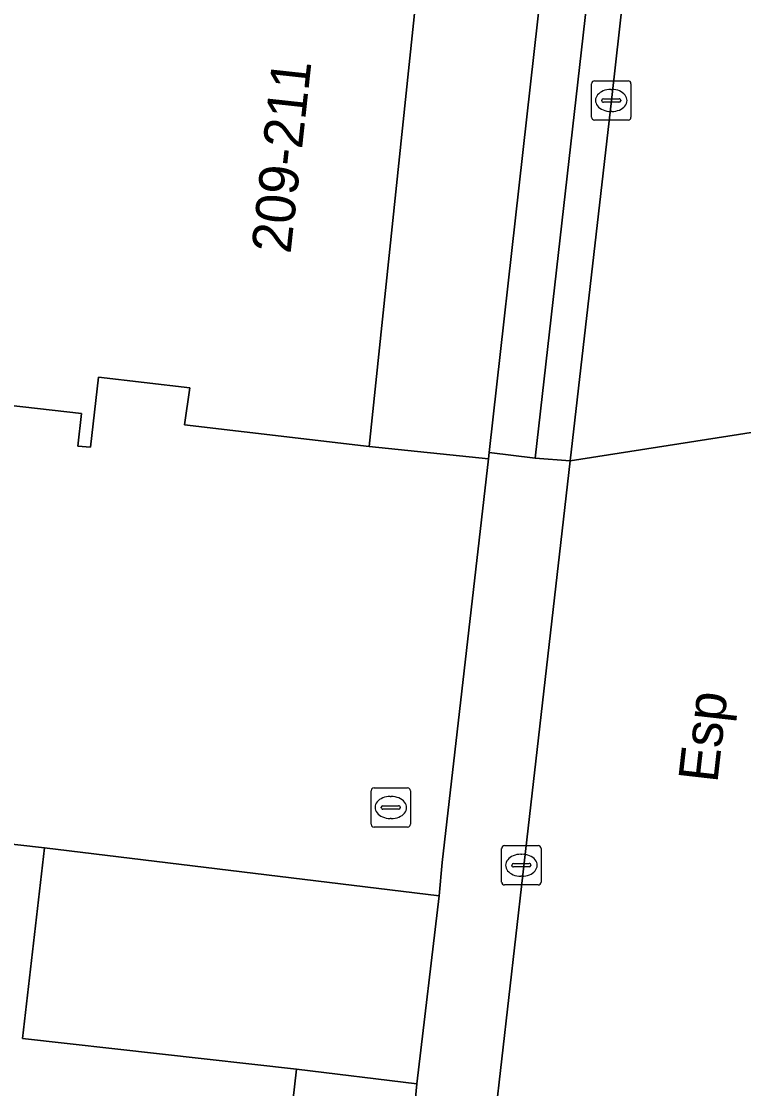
# Model space of a CAD drawing. Extents: x 161385 to 162589, y 388479 to 389756.
# Drawn here: x 162330.1 to 162348.45, y 388767.85 to 388794.97 of the extents above; entities that cross this region are included whole.
import ezdxf

# ---------------------------------------------------------------- set-up
doc = ezdxf.new("R2010")
doc.units = 0
for name, color, linetype in [('IMGEO_Berm_groen', 7, 'Continuous'), ('IMGEO_Erf', 7, 'Continuous'), ('IMGEO_Groenvoorziening', 7, 'Continuous'), ('IMGEO_Kolk', 7, 'Continuous'), ('IMGEO_Openbare_ruimte_label', 7, 'Continuous'), ('IMGEO_Pand', 7, 'Continuous'), ('IMGEO_Pand_nummerreeks', 7, 'Continuous'), ('IMGEO_Rijbaan_lokaal_gesloten', 7, 'Continuous'), ('IMGEO_Rioolput', 7, 'Continuous'), ('IMGEO_Voetpad_open', 7, 'Continuous')]:
    doc.layers.add(name, color=color, linetype=linetype)

msp = doc.modelspace()

# ---------------------------------------------------------------- linework, layer by layer
at = {"layer": 'IMGEO_Berm_groen'}
msp.add_lwpolyline([(162345.085, 388792.96), (162345.796, 388799.312), (162344.909, 388799.405), (162343.152, 388783.876), (162344.038, 388783.802)], close=True, dxfattribs=at)
at = {"layer": 'IMGEO_Erf'}
msp.add_lwpolyline([(162279.747, 388779.705), (162330.688, 388773.968), (162340.71, 388772.751), (162340.788, 388773.594), (162341.961, 388783.856), (162338.936, 388784.171), (162334.24, 388784.715), (162334.379, 388785.658), (162332.058, 388785.932), (162331.85, 388784.151), (162331.535, 388784.179), (162331.623, 388785.008), (162280.589, 388790.807)], dxfattribs=at)
at = {"layer": 'IMGEO_Groenvoorziening'}
msp.add_lwpolyline([(162343.021, 388800.103), (162340.623, 388800.353), (162338.936, 388784.171), (162341.961, 388783.856), (162341.98, 388784.02), (162343.689, 388799.274)], dxfattribs=at)
msp.add_lwpolyline([(162338.562, 388754.139), (162340.077, 388767.261), (162340.139, 388767.971), (162337.086, 388768.346), (162335.369, 388753.18), (162338.455, 388752.823)], close=True, dxfattribs=at)
at = {"layer": 'IMGEO_Kolk'}
for p, q in [((162344.657, 388793.461), (162345.509, 388793.461)), ((162344.582, 388792.535), (162344.582, 388793.387)), ((162345.07, 388793.241), (162345.095, 388793.241)), ((162345.583, 388793.387), (162345.583, 388792.535)), ((162344.841, 388792.955), (162344.841, 388792.967)), ((162345.279, 388792.918), (162344.881, 388792.918)), ((162344.884, 388793.004), (162345.282, 388793.004)), ((162345.325, 388792.967), (162345.325, 388792.955)), ((162345.093, 388792.681), (162345.068, 388792.681)), ((162345.509, 388792.461), (162344.657, 388792.461)), ((162342.298, 388773.102), (162342.298, 388773.954)), ((162342.373, 388774.028), (162343.225, 388774.028)), ((162343.299, 388773.954), (162343.299, 388773.102)), ((162342.786, 388773.808), (162342.811, 388773.808)), ((162342.557, 388773.522), (162342.557, 388773.534)), ((162342.995, 388773.485), (162342.597, 388773.485)), ((162342.6, 388773.571), (162342.998, 388773.571)), ((162343.041, 388773.534), (162343.041, 388773.522)), ((162342.809, 388773.248), (162342.784, 388773.248)), ((162343.225, 388773.028), (162342.373, 388773.028))]:
    msp.add_line(p, q, dxfattribs=at)
for points in [[(162344.657, 388793.461), (162345.509, 388793.461)], [(162344.582, 388792.535), (162344.582, 388793.387)], [(162345.583, 388793.387), (162345.583, 388792.535)], [(162345.509, 388792.461), (162344.657, 388792.461)], [(162342.298, 388773.102), (162342.298, 388773.954)], [(162342.373, 388774.028), (162343.225, 388774.028)], [(162343.299, 388773.954), (162343.299, 388773.102)], [(162343.225, 388773.028), (162342.373, 388773.028)]]:
    msp.add_lwpolyline(points, dxfattribs=at)
for centre, radius, start, end in [((162344.659, 388793.385), 0.0765, 91.552, 178.448), ((162344.659, 388793.385), 0.0765, 91.552, 178.448), ((162345.507, 388793.385), 0.0765, 1.552, 88.448), ((162345.507, 388793.385), 0.0765, 1.552, 88.448), ((162344.881, 388792.964), 0.0403, 85.8775, 175.7526), ((162344.878, 388792.954), 0.0366, 178.938, 274.7102), ((162345.282, 388792.961), 0.043, 264.8664, 352.4533), ((162345.286, 388792.966), 0.0386, 1.7309, 96.639), ((162344.659, 388792.537), 0.0765, 181.552, 268.448), ((162344.659, 388792.537), 0.0765, 181.552, 268.448), ((162345.507, 388792.537), 0.0765, 271.552, 358.448), ((162345.507, 388792.537), 0.0765, 271.552, 358.448), ((162342.375, 388773.952), 0.0765, 91.552, 178.448), ((162342.375, 388773.952), 0.0765, 91.552, 178.448), ((162343.223, 388773.952), 0.0765, 1.552, 88.448), ((162343.223, 388773.952), 0.0765, 1.552, 88.448), ((162342.597, 388773.531), 0.0403, 85.8775, 175.7526), ((162342.594, 388773.521), 0.0366, 178.938, 274.7102), ((162342.998, 388773.528), 0.043, 264.8664, 352.4533), ((162343.002, 388773.533), 0.0386, 1.7309, 96.639), ((162342.375, 388773.104), 0.0765, 181.552, 268.448), ((162342.375, 388773.104), 0.0765, 181.552, 268.448), ((162343.223, 388773.104), 0.0765, 271.552, 358.448), ((162343.223, 388773.104), 0.0765, 271.552, 358.448)]:
    msp.add_arc(centre, radius, start, end, dxfattribs=at)
for centre, major_axis, ratio, start_param, end_param in [((162345.069, 388792.961), (-0.387, 0.002), 0.722429, 4.712389, 7.853982), ((162345.094, 388792.961), (-0.39, 0.002), 0.717154, 1.570796, 4.712389), ((162342.785, 388773.528), (-0.387, 0.002), 0.722429, 4.712389, 7.853982), ((162342.81, 388773.528), (-0.39, 0.002), 0.717154, 1.570796, 4.712389)]:
    msp.add_ellipse(centre, major_axis=major_axis, ratio=ratio, start_param=start_param, end_param=end_param, dxfattribs=at)
at = {"layer": 'IMGEO_Pand'}
for points in [[(162334.332, 388806.326), (162283.02, 388812.167), (162280.589, 388790.807), (162331.623, 388785.008), (162331.535, 388784.179), (162331.85, 388784.151), (162332.058, 388785.932), (162334.379, 388785.658), (162334.24, 388784.715), (162338.936, 388784.171), (162340.623, 388800.353), (162340.638, 388800.493), (162333.756, 388801.193), (162334.321, 388806.194)], [(162335.369, 388753.18), (162337.086, 388768.346), (162330.125, 388769.129), (162330.688, 388773.968), (162279.747, 388779.705), (162277.505, 388759.734)]]:
    msp.add_lwpolyline(points, close=True, dxfattribs=at)
at = {"layer": 'IMGEO_Rijbaan_lokaal_gesloten'}
for points in [[(162364.598, 388917.339), (162355.936, 388879.524), (162354.085, 388871.528), (162350.544, 388841.795), (162349.892, 388835.959), (162348.515, 388823.765), (162348.397, 388822.686), (162347.549, 388814.966), (162346.508, 388805.67), (162345.796, 388799.312), (162345.085, 388792.96), (162344.038, 388783.802), (162351.507, 388784.973), (162351.586, 388785.803), (162354.609, 388813.12), (162354.707, 388814.075), (162359.887, 388860.235), (162360.209, 388863.109), (162360.509, 388865.779), (162360.606, 388866.537), (162361.541, 388871.709), (162361.659, 388872.226), (162367.76, 388898.886)], [(162344.45, 388723.253), (162346.266, 388739.136), (162347.508, 388750), (162351.507, 388784.973), (162344.038, 388783.802), (162342.836, 388773.285), (162342.124, 388767.05), (162340.637, 388753.967), (162340.189, 388750), (162339.087, 388740.255), (162338.482, 388734.9), (162338.192, 388732.338), (162337.703, 388727.976)]]:
    msp.add_lwpolyline(points, dxfattribs=at)
at = {"layer": 'IMGEO_Rioolput'}
for p, q in [((162338.981, 388774.57), (162338.981, 388775.422)), ((162339.056, 388775.496), (162339.908, 388775.496)), ((162339.982, 388775.422), (162339.982, 388774.57)), ((162339.283, 388775.039), (162339.681, 388775.039)), ((162339.469, 388775.276), (162339.494, 388775.276)), ((162339.24, 388774.99), (162339.24, 388775.002)), ((162339.678, 388774.953), (162339.28, 388774.953)), ((162339.724, 388775.002), (162339.724, 388774.99)), ((162339.908, 388774.496), (162339.056, 388774.496)), ((162339.492, 388774.716), (162339.467, 388774.716))]:
    msp.add_line(p, q, dxfattribs=at)
for points in [[(162338.981, 388774.57), (162338.981, 388775.422)], [(162339.056, 388775.496), (162339.908, 388775.496)], [(162339.982, 388775.422), (162339.982, 388774.57)], [(162339.908, 388774.496), (162339.056, 388774.496)]]:
    msp.add_lwpolyline(points, dxfattribs=at)
for centre, radius, start, end in [((162339.058, 388775.42), 0.0765, 91.552, 178.448), ((162339.058, 388775.42), 0.0765, 91.552, 178.448), ((162339.906, 388775.42), 0.0765, 1.552, 88.448), ((162339.906, 388775.42), 0.0765, 1.552, 88.448), ((162339.28, 388774.999), 0.0403, 85.8775, 175.7526), ((162339.685, 388775.001), 0.0386, 1.7309, 96.639), ((162339.277, 388774.989), 0.0366, 178.938, 274.7102), ((162339.681, 388774.996), 0.043, 264.8664, 352.4533), ((162339.058, 388774.572), 0.0765, 181.552, 268.448), ((162339.058, 388774.572), 0.0765, 181.552, 268.448), ((162339.906, 388774.572), 0.0765, 271.552, 358.448), ((162339.906, 388774.572), 0.0765, 271.552, 358.448)]:
    msp.add_arc(centre, radius, start, end, dxfattribs=at)
for centre, major_axis, ratio, start_param, end_param in [((162339.468, 388774.996), (-0.387, 0.002), 0.722429, 4.712389, 7.853982), ((162339.493, 388774.996), (-0.39, 0.002), 0.717154, 1.570796, 4.712389)]:
    msp.add_ellipse(centre, major_axis=major_axis, ratio=ratio, start_param=start_param, end_param=end_param, dxfattribs=at)
at = {"layer": 'IMGEO_Voetpad_open'}
for points in [[(162343.689, 388799.274), (162341.98, 388784.02), (162343.152, 388783.876), (162344.909, 388799.405), (162343.72, 388799.552)], [(162340.788, 388773.594), (162340.71, 388772.751), (162340.139, 388767.971), (162340.077, 388767.261), (162341.289, 388767.134), (162342.124, 388767.05), (162342.836, 388773.285), (162344.038, 388783.802), (162343.152, 388783.876), (162341.98, 388784.02), (162341.961, 388783.856)], [(162340.71, 388772.751), (162330.688, 388773.968), (162330.125, 388769.129), (162337.086, 388768.346), (162340.139, 388767.971)]]:
    msp.add_lwpolyline(points, close=True, dxfattribs=at)

# ---------------------------------------------------------------- texts
at = {"layer": 'IMGEO_Openbare_ruimte_label'}
msp.add_text('Esp', height=1, rotation=83.5143, dxfattribs=at).set_placement((162347.776, 388775.601))
at = {"layer": 'IMGEO_Pand_nummerreeks'}
msp.add_text('209-211', height=1, rotation=83.7697, dxfattribs=at).set_placement((162336.934, 388789.048))

doc.saveas('drawing.dxf')
